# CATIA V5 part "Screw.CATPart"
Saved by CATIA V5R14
Part number: Screw
Bounding box of the stored display mesh (mm): x -30 to 30, y -30 to 30, z -65 to 78
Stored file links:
  \\cdl-main\htdocs\wp-content\uploads\2016\CAD\example\07_DMU\DMU Kinematics_2016 (Part1)\1 Revolute Joint\Screw.CATPart
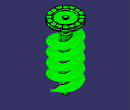
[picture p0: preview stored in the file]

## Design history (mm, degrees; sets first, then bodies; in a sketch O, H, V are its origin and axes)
Set1
  Point1: (10, 0, -45)
  Sketch1 on zx-plane, origin (0, 0, 0), H (-1, 0, 0), V (0, 0, 1)
    line L1 (0, -50) -> (0, 50)
    point P1 (0, -50)
    coincidence: P1 V
    vertical: L1 V
  Helix1: Direction Sketch1, RefPoint Point1, Pitch 20, Height 90, TaperAngle 0
  Plane1: type OffsetPt, RefPlane zx-plane, RefPoint Point1
  Sketch2 on Plane1, origin (0, 0, 0), H (-1, 0, 0), V (0, 0, 1)
    spline S1 through (-10, -43) (-19, -44) (-30, -45) (-19, -46) (-10, -47)
    line L1 (-10, -43) -> (-10, -47)
    point P1 (-10, -43)
    point P2 (-10, -47)
    point P3 (-10, -43)
    point P4 (-10, -47)
    coincidence: P3 P1, P4 P2
    vertical: L1 V
Body1 (main body)
  Sketch3 on xy-plane, origin (0, 0, 0), H (1, 0, 0), V (0, 1, 0)
    circle A1 centre (0, 0) radius 10
    radius A1 = 10
  Pad1: profile Sketch3, direction (0, 0, 1), length 50, mirrored extent
  Rib1: profile Sketch2, centre curve Helix1
  Sketch4 on start face of Pad1, origin (0, 0, -50), H (1, 0, 0), V (0, -1, 0)
    circle A1 centre (0, 0) radius 5
    radius A1 = 5
  Pad2: profile Sketch4, direction (0, 0, -1), length 15
  Sketch5 on end face of Pad1, origin (0, 0, 50), H (1, 0, 0), V (0, 1, 0)
    circle A1 centre (0, 0) radius 5
    radius A1 = 5
  Pad3: profile Sketch5, direction (0, 0, 1), length 20
  Sketch6 on zx-plane, origin (0, 0, 0), H (-1, 0, 0), V (0, 0, 1)
    point P1 (0, 78)
    line L1 (0, 78) -> (4, 78)
    line L2 (30, 78) -> (30, 76)
    line L3 (30, 70) -> (0, 70)
    line L4 (0, 70) -> (0, 78)
    line L5 (30, 76) -> (27, 75)
    line L6 (27, 75) -> (27, 73)
    line L7 (27, 73) -> (30, 72)
    point P8 (30, 72)
    line L8 (22, 78) -> (22, 78)
    line L9 (22, 78) -> (21, 78)
    line L10 (30, 72) -> (30, 70)
    line L11 (22, 78) -> (30, 78)
    line L12 (5, 78) -> (5, 78)
    line L13 (21, 78) -> (19, 76)
    line L14 (19, 76) -> (5, 76)
    line L15 (5, 76) -> (5, 77)
    line L16 (5, 77) -> (4, 78)
    coincidence: P1 V, P8 L2, L2 L10, L1 L11
    horizontal: L1 H, L3 H, L9 H, L11 H, L14 H
    vertical: L2 V, L4 V, L6 V, L10 V, L15 V
    perpendicularity: L16 L13
  Shaft1: profile Sketch6, axis axis of face of Pad3 from Sketch5.A1, angle 360
  Sketch7 on face of Shaft1 from Sketch6.L11, origin (0, 0, 78), H (1, 0, 0), V (0, 1, 0)
    arc A1 centre (0, 0) radius 21 from (-10.8867, 17.9577) to (-17.9577, 10.8867) ccw
    point P1 (21, 0)
    arc A2 centre (0, 0) radius 30 from (24.452, 17.381) to (17.381, 24.452) ccw
    point P2 (30, 0)
    line L1 (-5, 29.5804) -> (-5, 20.3961)
    line L2 (5, -29.5804) -> (5, -20.3961)
    line L3 (-29.5804, 5) -> (-20.3961, 5)
    line L4 (29.5804, -5) -> (20.3961, -5)
    line L5 (24.452, -17.381) -> (17.9577, -10.8867)
    line L6 (-24.452, 17.381) -> (-17.9577, 10.8867)
    line L7 (-24.452, -17.381) -> (-17.9577, -10.8867)
    line L8 (24.452, 17.381) -> (17.9577, 10.8867)
    line L9 (5, 20.3961) -> (5, 29.5804)
    point P4 (5, 20.3961)
    line L10 (10.8867, 17.9577) -> (17.381, 24.452)
    point P5 (10.8867, 17.9577)
    point P6 (17.9577, 10.8867)
    line L11 (20.3961, 5) -> (29.5804, 5)
    point P7 (20.3961, 5)
    point P8 (20.3961, -5)
    point P9 (17.9577, -10.8867)
    line L12 (10.8867, -17.9577) -> (17.381, -24.452)
    point P10 (10.8867, -17.9577)
    point P11 (5, -20.3961)
    line L13 (-5, -20.3961) -> (-5, -29.5804)
    point P12 (-5, -20.3961)
    line L14 (-10.8867, -17.9577) -> (-17.381, -24.452)
    point P13 (-10.8867, -17.9577)
    point P14 (-17.9577, -10.8867)
    line L15 (-20.3961, -5) -> (-29.5804, -5)
    point P15 (-20.3961, -5)
    point P16 (-20.3961, 5)
    line L16 (-10.8867, 17.9577) -> (-17.381, 24.452)
    arc A3 centre (0, 0) radius 21 from (-20.3961, 5) to (-20.3961, -5) ccw
    arc A4 centre (0, 0) radius 21 from (-17.9577, -10.8867) to (-10.8867, -17.9577) ccw
    arc A5 centre (0, 0) radius 21 from (-5, -20.3961) to (5, -20.3961) ccw
    arc A6 centre (0, 0) radius 21 from (10.8867, -17.9577) to (17.9577, -10.8867) ccw
    arc A7 centre (0, 0) radius 21 from (20.3961, -5) to (20.3961, 5) ccw
    arc A8 centre (0, 0) radius 21 from (17.9577, 10.8867) to (10.8867, 17.9577) ccw
    arc A9 centre (0, 0) radius 21 from (5, 20.3961) to (-5, 20.3961) ccw
    point P22 (29.5804, -5)
    point P23 (24.452, -17.381)
    point P24 (17.381, -24.452)
    point P25 (5, -29.5804)
    point P26 (-5, -29.5804)
    point P27 (-17.381, -24.452)
    point P28 (-24.452, -17.381)
    point P29 (-29.5804, -5)
    point P30 (-29.5804, 5)
    point P31 (-24.452, 17.381)
    point P32 (-17.381, 24.452)
    point P33 (-5, 29.5804)
    point P34 (5, 29.5804)
    arc A10 centre (0, 0) radius 30 from (5, 29.5804) to (-5, 29.5804) ccw
    arc A11 centre (0, 0) radius 30 from (-17.381, 24.452) to (-24.452, 17.381) ccw
    arc A12 centre (0, 0) radius 30 from (-29.5804, 5) to (-29.5804, -5) ccw
    arc A13 centre (0, 0) radius 30 from (-24.452, -17.381) to (-17.381, -24.452) ccw
    arc A14 centre (0, 0) radius 30 from (-5, -29.5804) to (5, -29.5804) ccw
    arc A15 centre (0, 0) radius 30 from (17.381, -24.452) to (24.452, -17.381) ccw
    arc A16 centre (0, 0) radius 30 from (29.5804, -5) to (29.5804, 5) ccw
    coincidence: A1 P1, P1 H, A2 P2, P2 H, A1 P4, L2 L9, A1 P5, L7 L10, A1 P6, A1 P7, L3 L11, A1 P8, A1 P9, A1 P10, L6 L12, A1 P11, A1 P12, A1 P13, A1 P14, A1 P15, A1 P16, A1 A3, A3 A4, A4 A5, A5 A6, A6 A7, A7 A8, A8 A9, A2 P22, A2 P23, A2 P24, A2 P25, A2 P26, A2 P27, A2 P28, A2 P29, A2 P30, A2 P31, A2 P32, A2 P33, A2 P34, A2 A10, A10 A11, A11 A12, A12 A13, A13 A14, A14 A15, A15 A16
    vertical: L1 V, L2 V, L9 V, L13 V
    horizontal: L3 H, L4 H, L11 H, L15 H
  Pocket1: profile Sketch7, direction (0, 0, -1), length 1
  Point2: type OnCurve, Support edge [face of Rib1 | face of Rib1], Ratio 0.5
